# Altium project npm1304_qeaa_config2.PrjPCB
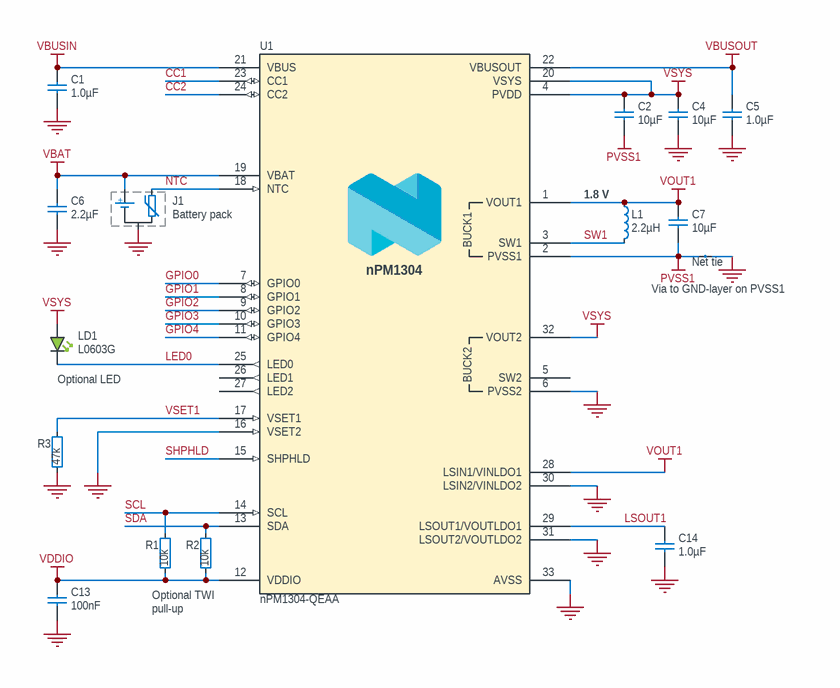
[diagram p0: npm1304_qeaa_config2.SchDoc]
1 sheet, 16 parts. Net scope: global (net labels, ports and power ports of the same name join across sheets).
Board file: npm1304_qeaa_config2.PcbDoc

## Sheet npm1304_qeaa_config2.SchDoc: nPM1304-QEAA Ref. Layout Config. 2
size A4; Revision: 1.0; SheetNumber: 1; SheetTotal: 1; DrawnBy: EISK; DocumentSize: A4; BoardTitle: nPM1304-QEAA Ref. Layout Config. 2; PCAName: nPM1304-QEAA; RefLayoutTitle: Simple – one BUCK, LOADSW and LED; Device: nPM1304-QEAA; Classification: PUBLIC; Config: 2

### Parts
C1  1.0µF  [CAPC1608X06L]
C2  10µF  [CAPC1608X06L]
C4  10µF  [CAPC1608X06L]
C5  1.0µF  [CAPC1608X06L]
C6  2.2µF  [CAPC1608X06L]
C7  10µF  [CAPC1608X06L]
C13  100nF  [CAPC0603X03L_C]
C14  1.0µF  [CAPC1608X06L]
J1  Battery pack  [TP_3x1mm_TH]  (graphical)
L1  2.2µH  [INDC2016X10N]
LD1  L0603G  [LED_0603_G]  (graphical)
NT1  Net tie  [2 PIN STARPOINT]  (net tie, no BOM)
R1  10k  [RESC0603X03L_C]
R2  10k  [RESC0603X03L_C]
R3  47k  [RESC0603X03L_C]
U1  nPM1304-QEAA  [Nordic_QFN50P500X500X90-33N]

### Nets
GND: C1.1 C4.1 C5.1 C6.1 C13.2 C14.1 J1.1(GND) NT1.1 R3.2 U1.6(PVSS2) U1.16(VSET2) U1.30(LSIN2/VINLDO2) U1.31(LSOUT2/VOUTLDO2) U1.33(AVSS)
PVSS1: C2.1 C7.1 NT1.2 U1.2(PVSS1)
VBAT: C6.2 J1.3(V+) U1.19(VBAT)
VBUSIN: C1.2 U1.21(VBUS)
VBUSOUT: C5.2 U1.22(VBUSOUT)
VDDIO: C13.1 R1.2 R2.2 U1.12(VDDIO)
VOUT1: C7.2 L1.1 U1.1(VOUT1) U1.28(LSIN1/VINLDO1)
VSYS: C2.2 C4.2 LD1.2(A) U1.4(PVDD) U1.20(VSYS) U1.32(VOUT2)
CC1: U1.23(CC1)
CC2: U1.24(CC2)
GPIO0: U1.7(GPIO0)
GPIO1: U1.8(GPIO1)
GPIO2: U1.9(GPIO2)
GPIO3: U1.10(GPIO3)
GPIO4: U1.11(GPIO4)
LED0: LD1.1(C) U1.25(LED0)
LSOUT1: C14.2 U1.29(LSOUT1/VOUTLDO1)
NTC: J1.2(NTC) U1.18(NTC)
SCL: R1.1 U1.14(SCL)
SDA: R2.1 U1.13(SDA)
SHPHLD: U1.15(SHPHLD)
SW1: L1.2 U1.3(SW1)
VSET1: R3.1 U1.17(VSET1)

Not connected (* = marked no-connect by the designer): U1 5(SW2) 26(LED1) 27(LED2)

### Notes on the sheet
- (near L1) 1.8 V
- (near NT1) Via to GND-layer on PVSS1
- (near LD1) Optional LED
- Optional TWI pull-up resistors

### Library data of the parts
C1 = C0603-1µ0-25V-X5R: Capacitor, X5R, ±10%, 25V; Manufacturer: N.A.; Part number NEMS: 100200687; Pad Count: 2; Component Status: Active
C2 C4 C7 = C0603-10µ-10V-X5R: Capacitor, Ceramic, X5R, ±20%, 10V; Manufacturer: N.A.; Part number Norautron: 262085341; Part number NEMS: 100200481; Pad Count: 2; Component Status: Active
C5 C14 = C0603-1µ0-10V-X5R: Capacitor, Ceramic, 1.0µF 10V X5R 0603,±10%; Manufacturer: N.A.; Part number NEMS: 100200528; Pad Count: 2; Component Status: Active
C6 = C0603-2µ2-25V-X5R-GRM188R61E225KA12D: Capacitor, Ceramic, X5R, ±10%, 25V; Manufacturer: Murata; Part number NEMS: 100200454; Component Status: Active; Pad Count: 2; Artikkelnr Noca: N.A.
C13 = C0201-100n-25V-X5R: Capacitor, Ceramic, X5R, ±10%, 25V; Manufacturer: Murata; Manufacturer Part Number: GRM033R61E104KE14J; Part number NEMS: 100200459; Pad Count: 2; Artikkelnr Noca: N.A.; Component Status: Active
J1 = Battery_w/NTC_TP: Battery pack with NTC; Manufacturer: N.A.; Part number NEMS: 101800005; Pad Count: 3; Component Status: Active
L1 = L0806-2µ2-2500mA-73mOhm-CIGT201610EH2R2MNE: Inductor, Irms=2.5A, Isat=2.9A, ±20%, DCR=73mΩ; Manufacturer: Samsung Electro-Mechanics America; Part number Norautron: 26521789; Part number NEMS: 100300400; Pad Count: 2; Note: Unshielded Thin Film Inductor; Artikkelnr Noca: N.A.; Component Status: Active
LD1 = 150060GS55040: LED 0603 GREEN; Manufacturer: Wurth Elektronik; Part number NEMS: 101400140; Component Status: Active; Pad Count: 2; Note: 60 mcd @ 20 mA; Artikkelnr Noca: N.A.
NT1 = 2 pin starpoint: Starpoint; Manufacturer: N.A.; Part number NEMS: 100500603; Pad Count: 2; Component Status: Active
R1 R2 = R0201-10k: Resistor, ±1%, 0.05W; Manufacturer: N.A.; Part number IPS: 00000001255; Part number Norautron: 26107101; Part number NEMS: 100100065; Pad Count: 2; Note: Chip Res 1%; Component Status: Active
R3 = R0201-47k: Resistor, ±1%, 0.05W; Manufacturer: N.A.; Part number IPS: 00000001423; Part number NEMS: 100100076; Component Status: Active; Pad Count: 2; Note: Chip Res 1%
U1 = nPM1304-QEAA: Li-Ion/Li-Polymer USB-C battery charger with high efficiency buck regulators, LDOs or load switches, LED drivers, TWI and VBUSOUT; Manufacturer: Nordic Semiconductor; Part number NEMS: 102000396; Component Status: Active; Pad Count: 33; Artikkelnr Noca: N.A.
